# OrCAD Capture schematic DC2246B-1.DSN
size Custom; title: 20V, 200mA, ULTRALOW NOISE,; rev: 1; note: DC2246B
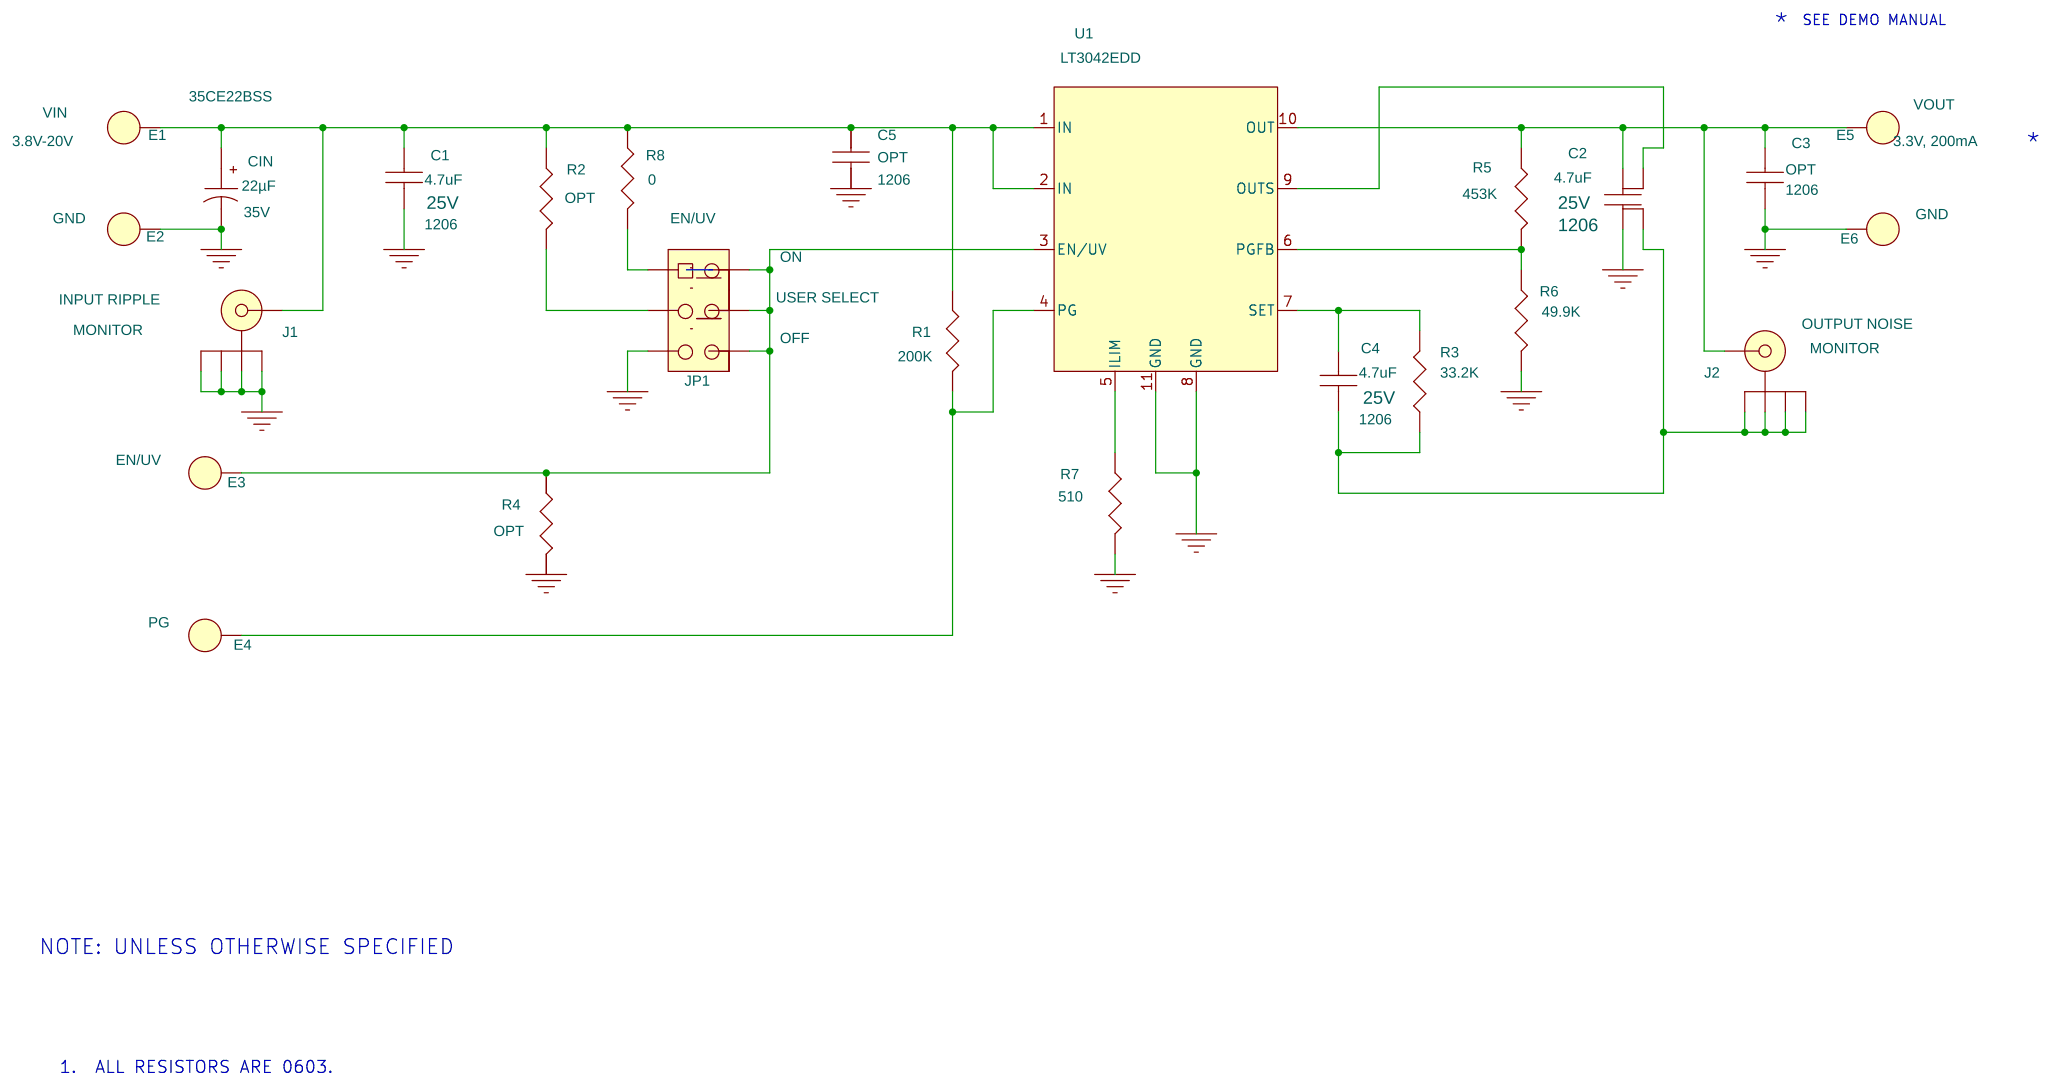
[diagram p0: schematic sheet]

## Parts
C1  4.7uF  [1206]
C2  4.7uF  [1206S-SP-SAME4]
C3  OPT  [1206]
C4  4.7uF  [1206]
C5  OPT  [1206]
CIN  22µF  [CAP-CE-5X5.4]
E1  VIN  [MM/2501]
E2  GND  [MM/2501]
E3  EN/UV  [MM/2501]
E4  PG  [MM/2501]
E5  3.3V, 200mA  [MM/2501]
E6  GND  [MM/2501]
J1  MONITOR  [BNC5]
J2  MONITOR  [BNC5]
JP1  JP2X3/079  [JP2X3/079]
R1  200K  [0603]
R2  OPT  [0603]
R3  33.2K  [0603]
R4  OPT  [0603]
R5  453K  [0603]
R6  49.9K  [0603]
R7  510  [0603]
R8  0  [0603]
U1  LT3042EDD  [DD]

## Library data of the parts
C1 C4 = CAP_NP: 1ST PART FIELD: 25V
C2 = CAP_NP_0: 1ST PART FIELD: 25V; 2nd Part Field: 1206
C3 = CAP_NP
C5 = CAP_NP: 1ST PART FIELD: 50V; 2nd Part Field: 10uF
CIN = 50CE10BSS: 1st Part Field: 35V; 5TH PART FIELD: 35CE22BSS
E1 = MillMax-2501_2: 1ST PART FIELD: *; Value1: 3.8V-20V
E2-E4 E6 = MillMax-2501_2
E5 = MillMax-2501_2: VALUE1: VOUT
J1 = BNC_0: 1ST PART FIELD: INPUT RIPPLE
J2 = BNC_0: 1ST PART FIELD: OUTPUT NOISE
JP1 = JP2X3_079: 1ST PART FIELD: ON; 2nd Part Field: OFF; 3rd Part Field: USER SELECT; 4TH PART FIELD: EN/UV
R1-R8 = R: V: 1%
U1 = LT3042EDD_1

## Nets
GND: C1.2 C2.1 C3.2 C5.2 CIN.2 E2.1 E6.1 J1.2 J1.3 J1.4 J1.5 JP1.5 R4.2 R6.2 R7.2 U1.8(GND) U1.11(GND)
N16788420: C1.1 C5.1 CIN.1 E1.1 J1.1 R1.1 R2.1 R8.1 U1.1(IN) U1.2(IN)
N16788443: C2.2 C3.1 E5.1 J2.1 R5.1 U1.10(OUT)
N16788453: JP1.3 R2.2
N16788459: R7.1 U1.5(ILIM)
N16788606: E4.1 R1.2 U1.4(PG)
N16788632: C4.1 R3.2 U1.7(SET)
N16788704: C2.4 U1.9(OUTS)
N16788734: C2.3 C4.2 J2.2 J2.3 J2.4 J2.5 R3.1
N16788738: R5.2 R6.1 U1.6(PGFB)
N16814141: E3.1 JP1.2 JP1.4 JP1.6 R4.1 U1.3(EN/UV)
N16830162: JP1.1 R8.2

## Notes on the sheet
- *
- SEE DEMO MANUAL
- *
- NOTE: UNLESS OTHERWISE SPECIFIED
- 1.  ALL RESISTORS ARE 0603.
